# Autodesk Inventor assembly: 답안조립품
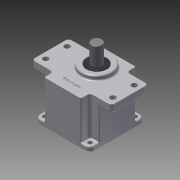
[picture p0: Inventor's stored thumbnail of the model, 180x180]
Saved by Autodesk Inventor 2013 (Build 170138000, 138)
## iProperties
Created: 2015-07
Part Number: 답안조립품
Document SubType Name: Assembly
Designer: user
Author: user
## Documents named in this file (12)
- C:\Users\user\Desktop\450734V1002\답안조립품.iam
- C:\Users\user\Desktop\450734V1002\본체.ipt
- C:\Users\user\Desktop\450734V1002\서브축.ipt
- C:\Users\user\Desktop\450734V1002\메인축.ipt
- C:\Users\user\Desktop\450734V1002\베어링 6003.ipt
- 베어링 6003.ipt
- C:\Users\user\Desktop\450734V1002\베어링 608.ipt
- 베어링 608.ipt
- C:\Users\user\Desktop\450734V1002\커버.ipt
- C:\Users\user\Desktop\450734V1002\오일실 17x32x8.ipt
- C:\Users\user\Desktop\450734V1002\오일실 8x22x7.ipt
- C:\Users\user\Desktop\450734V1002\M4x0.5x16.ipt
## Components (4 placed, 1 different names)
1. M4x0.5x12:1
2. M4x0.5x12:2
3. M4x0.5x12:3
4. M4x0.5x12:4
